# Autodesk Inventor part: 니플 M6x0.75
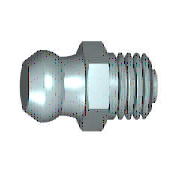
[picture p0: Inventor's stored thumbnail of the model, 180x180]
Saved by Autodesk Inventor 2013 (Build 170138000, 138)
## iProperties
IsCustomPart: 1
Created: 2012-02
Part Number: 니플 M6x0.75
Material: 강철, 연강
Description: 윤활 니플, 원추 유형 A
Document SubType Name: Modeling
Standard: JIS B 1575
Designer: mduedu
Standards Organization: JIS
Language: ko-KR
Size Designation: MT 6 x 0.75
Categories: <MemberInstance><Categories><Category DisplayName="기타 부품" InternalName="5aa15e00-363f-49f2-933f-16f664388e3f" Mnemonic="OTHER"><Category DisplayName="그리스 부속품" I
Density: 1 g/cm^3
Author: mduedu
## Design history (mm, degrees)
sketch "스케치1"
  geometry: L1 (-8.8, 0)-(-8.8, 2.4); L2 (-8.8, 2.4)-(-7.335, 3.202); L3 (-8.8, 0)-(4.7, 0); L4 (4.7, 0)-(4.7, 1.5); L5 (4.7, 1.5)-(4, 1.5); L6 (4, 1.5)-(4, 3); L7 (4, 3)-(0, 3); L8 (-11.5, 0)-(7.4, 0) reference; L9 (0, -1.733)-(0, 10.398) reference; L10 (-3, 3.5)-(0, 3.5); L11 (0, 3.5)-(0, 3); A1 r 3.3 centre (-6.535, 0) between (-4.789, 2.8) and (-7.335, 3.202); A2 r 6 centre (-6.053, 8.665) between (-4.789, 2.8) and (-3, 3.5)
  constraints: 18 end point, 5 perpendicular, 4 point on circle, 2 centre point, 2 parallel, 2 point on line, 1 collinear, 1 vertical
  dimensions: "d0" = 13.5 distance between parallel lines of L1 L4 (= GL); "d1" = 5.6 diameter of A1.start L3 (= KGB2); "d2" = 0.7 distance between parallel lines of L4 L6 (= PHH); "d3" = 3 diameter of L5 L3 (= 0.5 x NND); "d4" = 6 diameter of L7 L3 (= NND); "d5" = 6.6 dimension on A1 L3 (= KR); "d6" = 4.8 diameter of L1.end L3 (= KGB1); "d7" = 6 radius of A2 (= RBN); "d11" = 7 diameter of L10.start L3 (= SW); "d14" = 3 distance of L10.start L10.end (= KOH); "d15" = 4 distance between parallel lines of L6 L11 (= NLG); "d61" = 7.33505 distance from line of L9 L2.end (computed from KGB1, KR, PHH, GL, NLG, VERS); "d62" = 6.53505 distance from line of L9 A1.centre (computed from NLG, GL, PHH, KR, KGB1)
revolve "본체" sketch "스케치1" stored, may be unused: angle "d25" = 90 deg
sketch "스케치2"
  geometry: L1 (2.021, 3.5)-(4.041, 0); L2 (4.041, 0)-(2.021, -3.5); L3 (2.021, -3.5)-(-2.021, -3.5); L4 (-2.021, -3.5)-(-4.041, 0); L5 (-4.041, 0)-(-2.021, 3.5); L6 (-2.021, 3.5)-(2.021, 3.5); C1 r 3.5 at (0, 0) reference; 1 further point
  constraints: 12 end point, 1 coincident, 1 horizontal, 1 tangent, 11 other
extrude "머리" join sketch "스케치2" distance "d17" = 3 (= KOH); taper "d18" = 0 deg
sketch "스케치3"
  geometry: L1 (2.687, 4.041)-(3, 4.041); L2 (3, 4.041)-(3, 3.5); L3 (3, 3.5)-(2.687, 4.041); L4 (0.313, 4.041)-(0, 4.041); L5 (0, 4.041)-(0, 3.5); L6 (0, 3.5)-(0.313, 4.041); L7 (3.6, 0)-(-0.6, 0) reference; L8 (0, 4.041)-(0, 2.021) reference; L9 (0, 4.041)-(3, 4.041) reference; L10 (3, 3.031)-(3, 4.041) reference
  constraints: 12 end point, 4 collinear, 3 perpendicular, 1 horizontal
  dimensions: "d19" = 3.5 distance from line of L5.end L7 (= 0.5 x SW); "d20" = 3.5 distance from line of L2.end L7 (= 0.5 x SW); "d21" = 30 deg angle of L6 L5; "d22" = 30 deg angle of L2 L3
revolve "모따기1" sketch "스케치3" stored, may be unused: angle "d56" = 90 deg
body "Solid1"
fillet "모깎기1" dims "d8" = 0.2 (= RR)
feature "스레드1" dims "d9" = 3.53991 (= NLG - GAL), "d10" = 0
chamfer "모따기2" distance "d23" = 0.46009 (= -0.5 x GD1 + 0.5 x NND); stored, may be unused: angle "d24" = 45 deg, second distance "d59" = 0.46009 (= -0.5 x GD1 + 0.5 x NND)
other parameters: "NLG" = 4 [user parameter; used in 4 equation terms], "GL" = 13.5 [user parameter; used in 3 equation terms], "NND" = 6 [user parameter; used in 4 equation terms], "KGB1" = 4.8 [user parameter; used in 3 equation terms], "KGB2" = 5.6 [user parameter; used in 1 equation term], "VERS" = 0.8 [user parameter; used in 1 equation term], "KR" = 6.6 [user parameter; used in 3 equation terms], "RBN" = 6 [user parameter; used in 1 equation term], "SW" = 7 [user parameter; used in 3 equation terms], "KOH" = 3 [user parameter; used in 2 equation terms], "GAL" = 0.46009 (= 0.61345 x PTC) [user parameter; used in 1 equation term], "FAWI" = 45 deg [user parameter], "PHH" = 0.7 [user parameter; used in 3 equation terms], "GD1" = 5.07983 (= THREADDIA - 1.2269 x PTC) [user parameter; used in 2 equation terms], "RR" = 0.2 [user parameter; used in 1 equation term], "d12" = 0, "d13" = 0, "GUL" = 0.46009 (= 0.61345 x PTC) [user parameter], "TPU" = 13.33333 (computed from PTC) [user parameter], "DULO" = 1.5 [user parameter], "PTC" = 0.75 [user parameter; used in 4 equation terms], "GEL" = 4 [user parameter], "THREADDIA" = 6 [user parameter; used in 1 equation term], "TOA" = 30 deg [user parameter]
